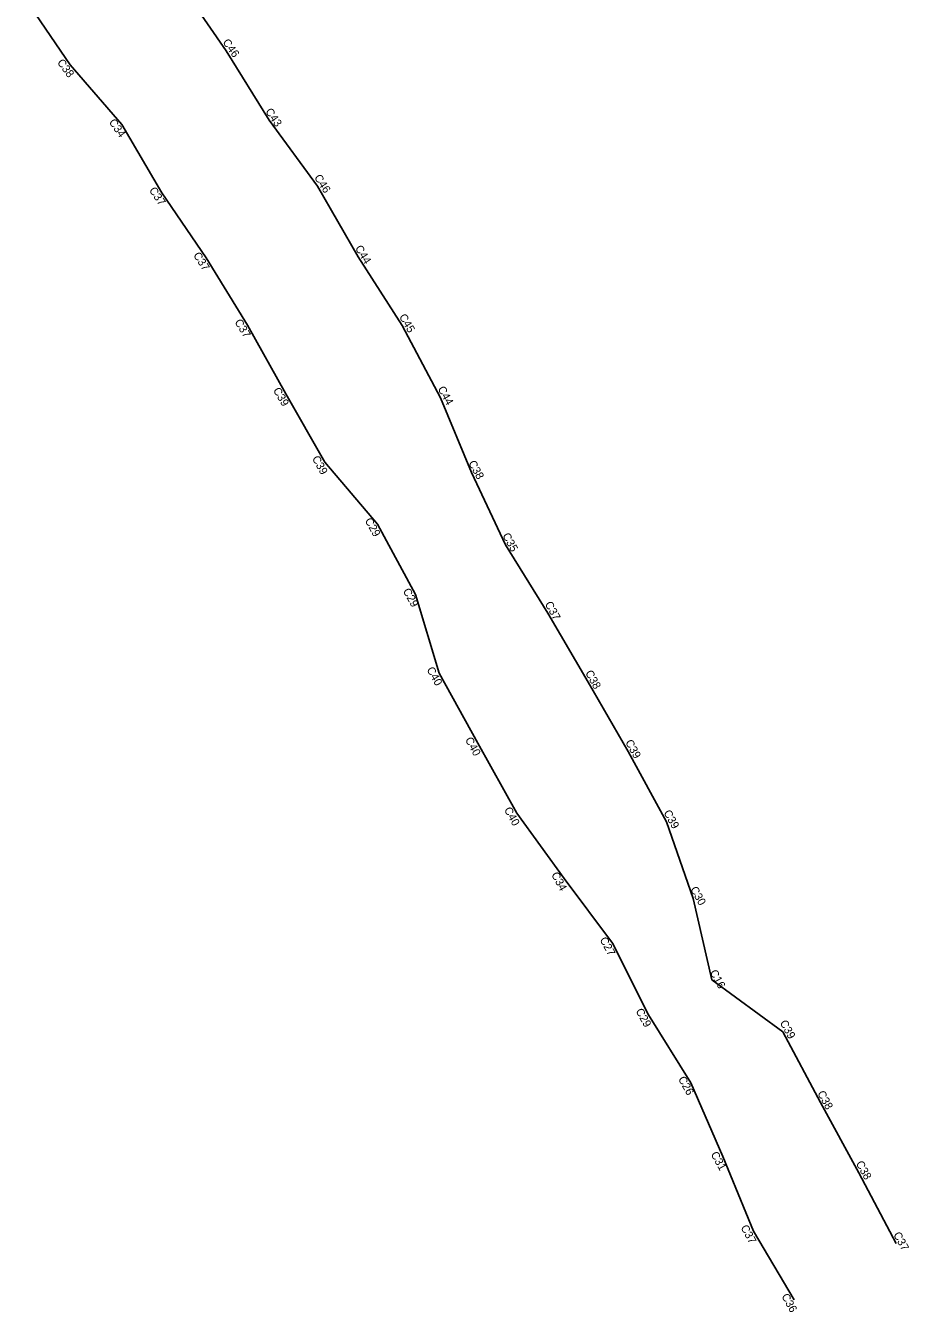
# Model space of a CAD drawing. Extents: x 2164037 to 2171931, y 206073 to 210167.
# Drawn here: x 2171379 to 2171931, y 206073 to 206877 of the extents above; entities that cross this region are included whole.
import ezdxf

# ---------------------------------------------------------------- set-up
doc = ezdxf.new("R2010")
doc.units = 0
doc.layers.add('RD_PD_CstnLmt', color=7, linetype='Continuous')
doc.layers.add('RD_PD_TX_CstnLmt', color=7, linetype='Continuous')

msp = doc.modelspace()

# ---------------------------------------------------------------- linework, layer by layer
at = {"layer": 'RD_PD_CstnLmt'}
for p, q in [((2171475.23, 206902.93), (2171504.21, 206860.94)), ((2171379.01, 206892.86), (2171406.82, 206852.2)), ((2171504.21, 206860.94), (2171530.96, 206817.47)), ((2171406.82, 206852.2), (2171439.09, 206814.79)), ((2171439.09, 206814.79), (2171464.1, 206772.23)), ((2171530.96, 206817.47), (2171561.25, 206776.4)), ((2171561.25, 206776.4), (2171586.64, 206732.15)), ((2171464.1, 206772.23), (2171491.66, 206731.48)), ((2171491.66, 206731.48), (2171517.45, 206689.57)), ((2171586.64, 206732.15), (2171614.12, 206689.21)), ((2171517.45, 206689.57), (2171541.52, 206646.67)), ((2171614.12, 206689.21), (2171638.06, 206644.2)), ((2171541.52, 206646.67), (2171565.82, 206603.94)), ((2171638.06, 206644.2), (2171657.35, 206597.56)), ((2171565.82, 206603.94), (2171598.74, 206565.16)), ((2171657.35, 206597.56), (2171678.65, 206552.2)), ((2171598.74, 206565.16), (2171622.53, 206521.18)), ((2171678.65, 206552.2), (2171705.03, 206509.66)), ((2171622.53, 206521.18), (2171637.3, 206472.21)), ((2171705.03, 206509.66), (2171730.36, 206466.53)), ((2171637.3, 206472.21), (2171661.29, 206428.34)), ((2171730.36, 206466.53), (2171755.33, 206423.2)), ((2171661.29, 206428.34), (2171685.64, 206384.67)), ((2171755.33, 206423.2), (2171779.24, 206379.29)), ((2171685.64, 206384.67), (2171715.22, 206343.89)), ((2171779.24, 206379.29), (2171795.93, 206331.38)), ((2171715.22, 206343.89), (2171745.38, 206303.43)), ((2171795.93, 206331.38), (2171807.45, 206280.62)), ((2171745.38, 206303.43), (2171767.91, 206258.76)), ((2171807.45, 206280.62), (2171851.84, 206248.03)), ((2171767.91, 206258.76), (2171794.46, 206216.3)), ((2171851.84, 206248.03), (2171875.3, 206203.87)), ((2171794.46, 206216.3), (2171814.32, 206170.15)), ((2171875.3, 206203.87), (2171899.38, 206160.04)), ((2171814.32, 206170.15), (2171833.43, 206123.58)), ((2171899.38, 206160.04), (2171922.65, 206115.78)), ((2171833.43, 206123.58), (2171858.99, 206080.58))]:
    msp.add_line(p, q, dxfattribs=at)

# ---------------------------------------------------------------- texts
at = {"layer": 'RD_PD_TX_CstnLmt'}
for s, rotation, p in [('C46', 305.31989, (2171501.7, 206866.22)), ('C38', 306.55738, (2171398.37, 206853.52)), ('C43', 304.0824, (2171528.41, 206823.03)), ('C34', 305.31989, (2171430.7, 206816.25)), ('C46', 302.84491, (2171558.97, 206781.79)), ('C37', 304.0824, (2171455.81, 206773.77)), ('C37', 302.84491, (2171483.41, 206733.2)), ('C44', 301.60742, (2171584.47, 206737.59)), ('C45', 300.36993, (2171611.99, 206694.83)), ('C37', 301.60742, (2171509.23, 206691.48)), ('C39', 300.36993, (2171533.29, 206648.85)), ('C44', 299.13244, (2171636.13, 206649.73)), ('C39', 299.13244, (2171557.63, 206606.29)), ('C38', 298.938, (2171655.27, 206603.38)), ('C29', 298.938, (2171590.59, 206567.51)), ('C35', 298.938, (2171676.52, 206558.11)), ('C29', 298.938, (2171614.38, 206523.53)), ('C37', 298.938, (2171703.04, 206515.33)), ('C40', 298.938, (2171629.22, 206474.42)), ('C38', 298.938, (2171728.28, 206472.35)), ('C40', 298.938, (2171653.21, 206430.55)), ('C39', 298.938, (2171753.28, 206428.97)), ('C40', 298.938, (2171677.56, 206386.88)), ('C39', 298.938, (2171777.19, 206385.06)), ('C34', 298.938, (2171707.05, 206346.28)), ('C30', 298.938, (2171793.85, 206337.23)), ('C27', 298.938, (2171737.28, 206305.68)), ('C16', 298.938, (2171806.03, 206285.25)), ('C29', 298.938, (2171759.75, 206261.11)), ('C39', 298.938, (2171849.79, 206253.8)), ('C26', 298.938, (2171786.31, 206218.65)), ('C38', 298.938, (2171873.22, 206209.69)), ('C31', 298.938, (2171806.64, 206171.64)), ('C38', 298.938, (2171897.3, 206165.87)), ('C37', 298.938, (2171825.31, 206125.86)), ('C37', 298.938, (2171920.66, 206121.45)), ('C36', 298.938, (2171850.81, 206082.96))]:
    msp.add_text(s, height=5, rotation=rotation, dxfattribs=at).set_placement(p)

doc.saveas('drawing.dxf')
